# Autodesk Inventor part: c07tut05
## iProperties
Shininess: 64.0
Length Units: 11269
Angle Units: 11279
Time Units: 11290
Mass Units: 11283
Length Display Precision: 3
Angle Display Precision: 2
Compacted: True
Part Number: c07tut05
Document SubType Name: Modeling
Created: 2002-12
Designer: deepak
Density: 1 g/cm^3
Density: 0.0
Volumn: 0.0
Area: 0.0
PropertySet Name: Model Information
Control State: 0
Master: False
Checked Out: False
Author: deepak
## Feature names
1. Loft3
